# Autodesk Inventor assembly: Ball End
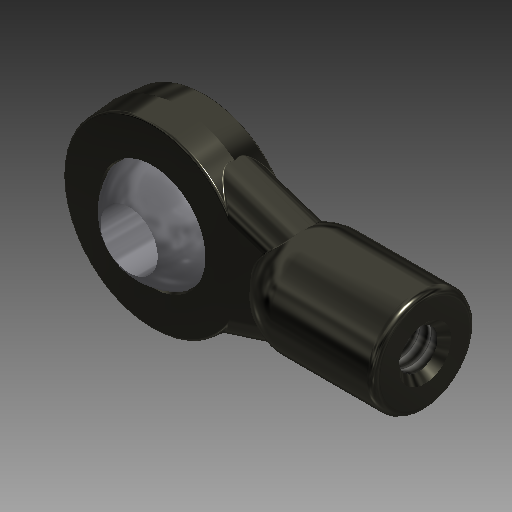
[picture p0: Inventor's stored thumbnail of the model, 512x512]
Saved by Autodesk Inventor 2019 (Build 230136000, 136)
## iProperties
Shininess: 50.0
Compacted: True
Length Units: 11272
Angle Units: 11279
Time Units: 11290
Mass Units: 11286
Length Display Precision: 4
Angle Display Precision: 2
Company: Autodesk
Manager: Lebovitz
Created: 2000-03
Part Number: Ball End
Project: Inventor Samples
User Status: IN PROGRESS
Document SubType Name: Assembly
Designer: The PD Team
Mass: 0.70348 g
Surface Area: 6.19952 cm^2
Volume: 0.425844 cm^3
Density: 1.65196 g/cm^3
Description: asd
Cost Center: Core
Checked By: Mango
Engineer: Bananajoe
Engr Approved By: Bananajoe
Mfg Approved By: Mango
Density: 0.0
Volumn: 0.0
Area: 0.0
PropertySet Name: Model Information
Control State: 0
Master: False
Checked Out: False
Checked Out Date: 2018-05-30
Last Check In Date: 2018-05-30
Author: The PD Team
Revision Number: A
Title: Ball End
Comments: New Revision
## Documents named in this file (3)
- C:\Users\itools\Desktop\autodesk_inventor_2018_samples\Models\Assemblies\Suspension\Components\Ball End.iam
- C:\Users\itools\Desktop\autodesk_inventor_2018_samples\Models\Assemblies\Suspension\Components\Ball End.ipt
- C:\Users\itools\Desktop\autodesk_inventor_2018_samples\Models\Assemblies\Suspension\Components\0.25 Ball.ipt
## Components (2 placed, 2 different names)
1. Ball End:1 — Mate:1, Angle:1
2. 0.25 Ball:1 — Mate:1, Angle:1
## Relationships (2: Mate 1, Angle 1)
- Mate:1: Ball End:1 ↔ 0.25 Ball:1
- Angle:1: Ball End:1 ↔ 0.25 Ball:1
